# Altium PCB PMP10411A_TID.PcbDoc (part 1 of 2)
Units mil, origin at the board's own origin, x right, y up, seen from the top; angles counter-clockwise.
Board outline 3000 x 2000 mil, 4 copper layers (Top Layer, Signal Layer 1, Signal Layer 2, Bottom Layer), stack 63.634 mil thick; 167 components, 63 nets, 404 pads, 19 vias.
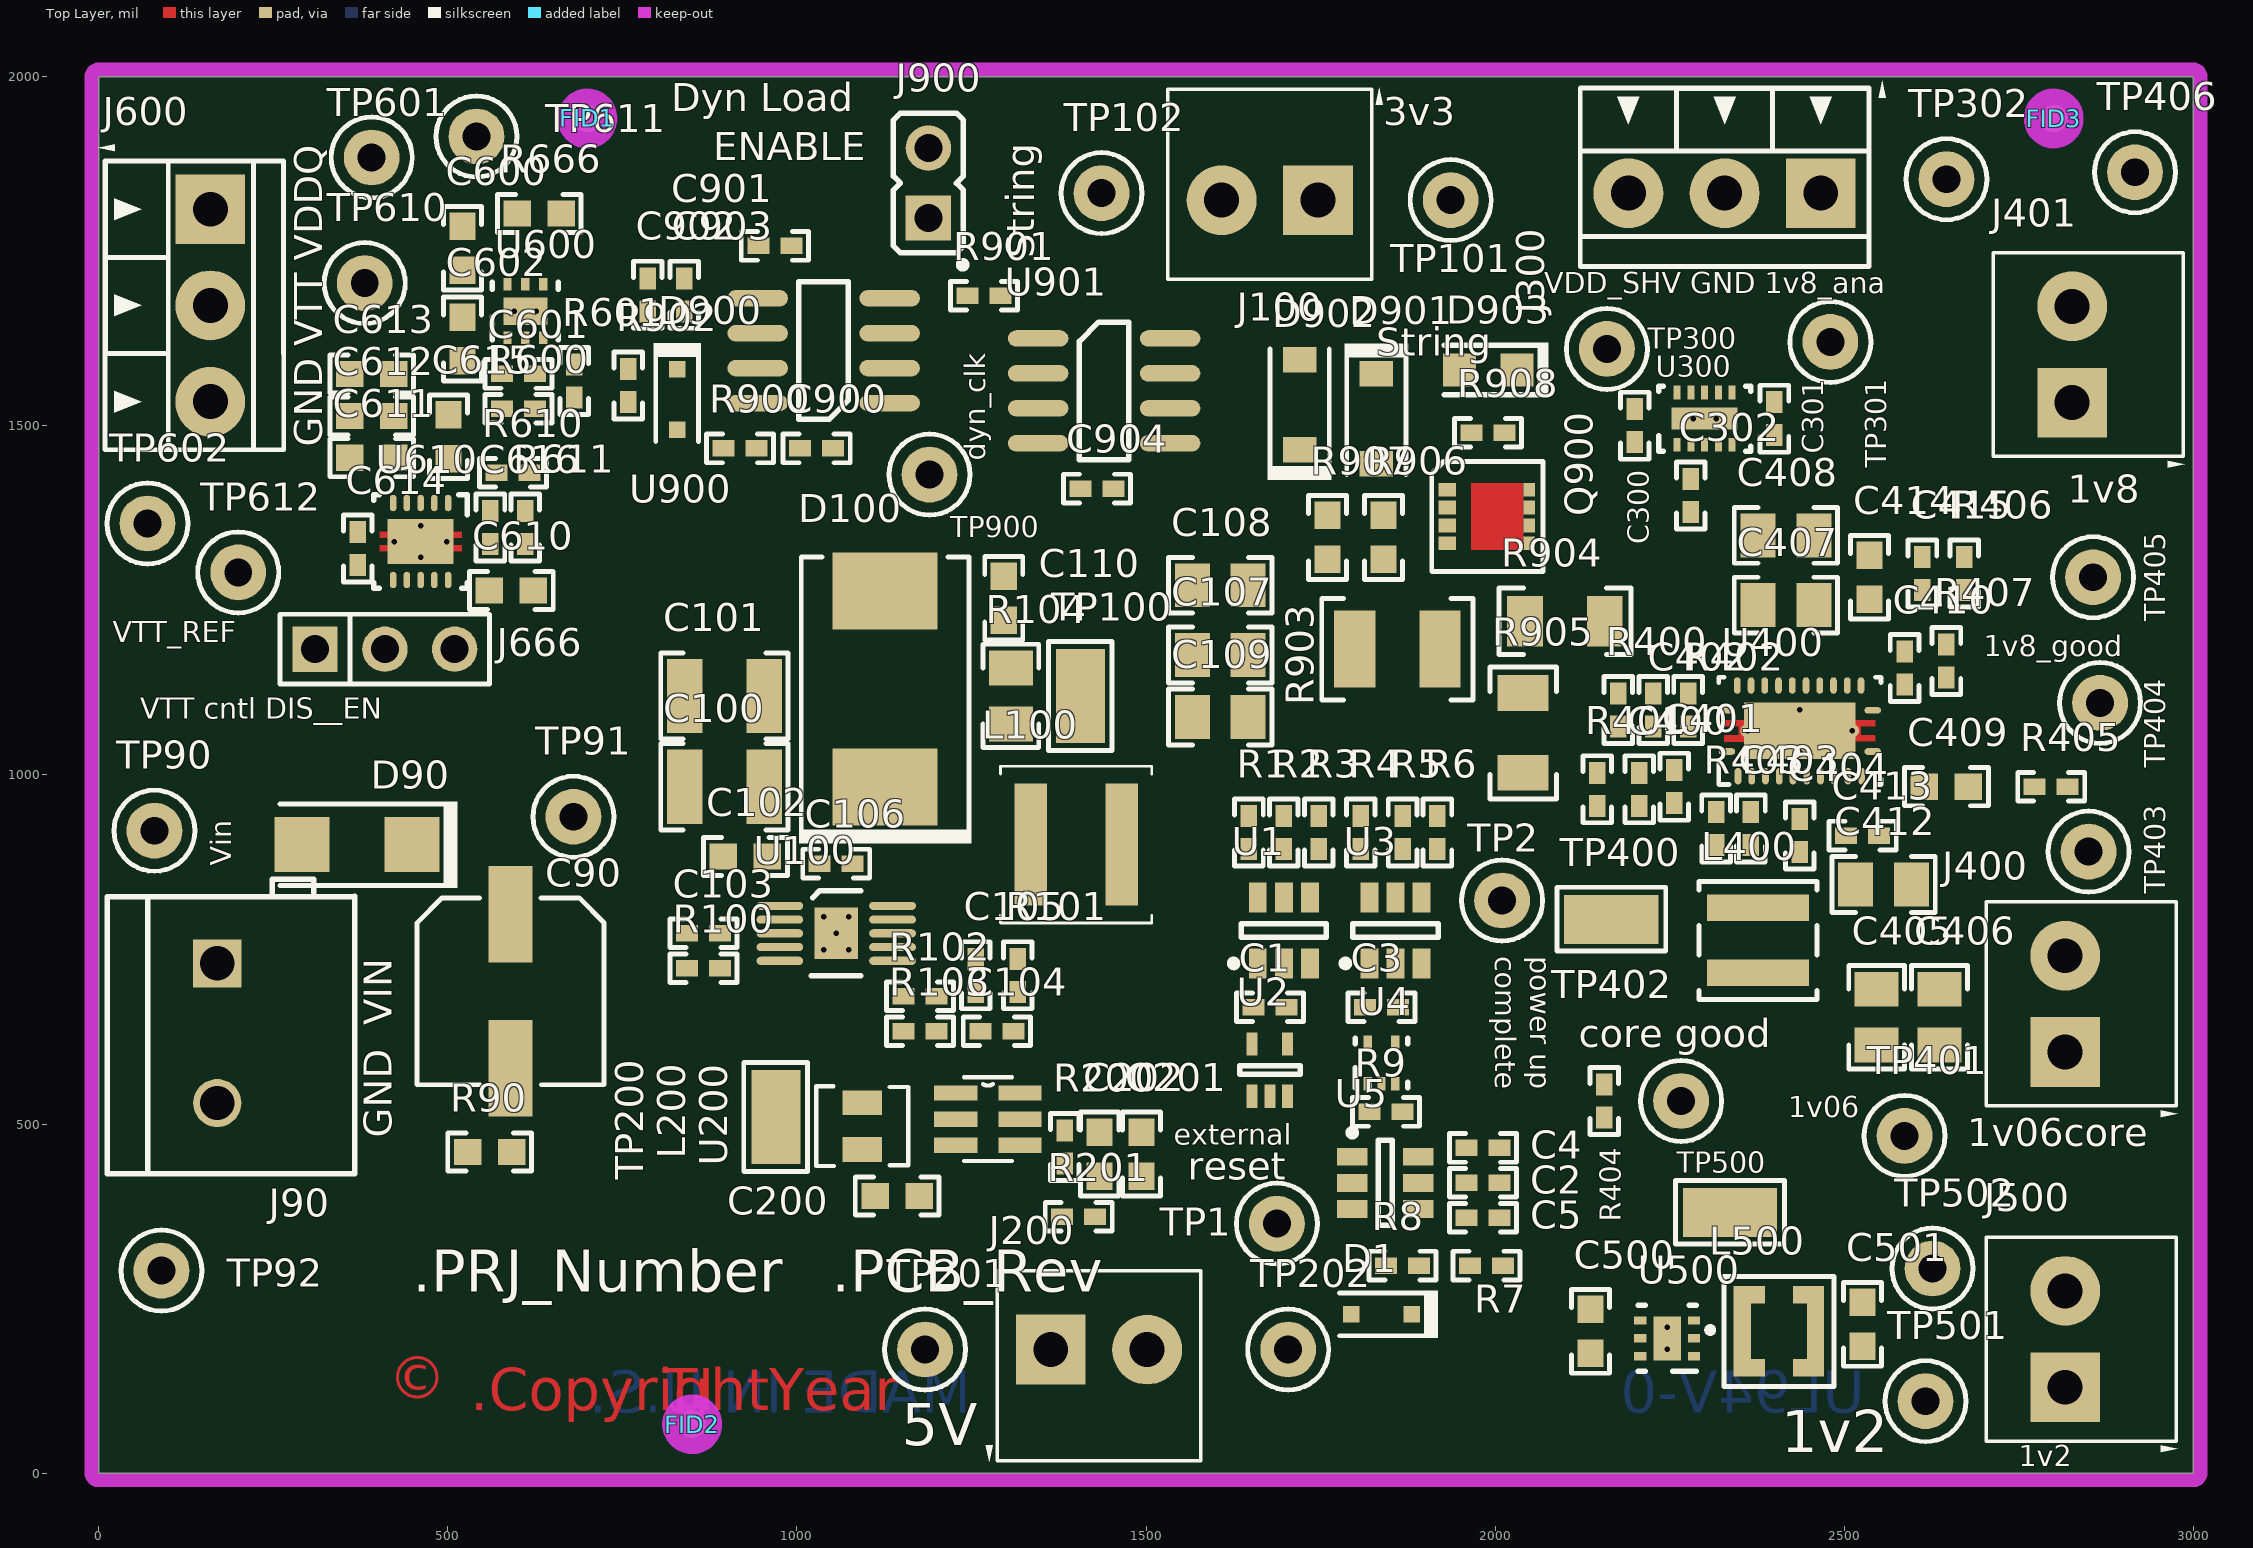
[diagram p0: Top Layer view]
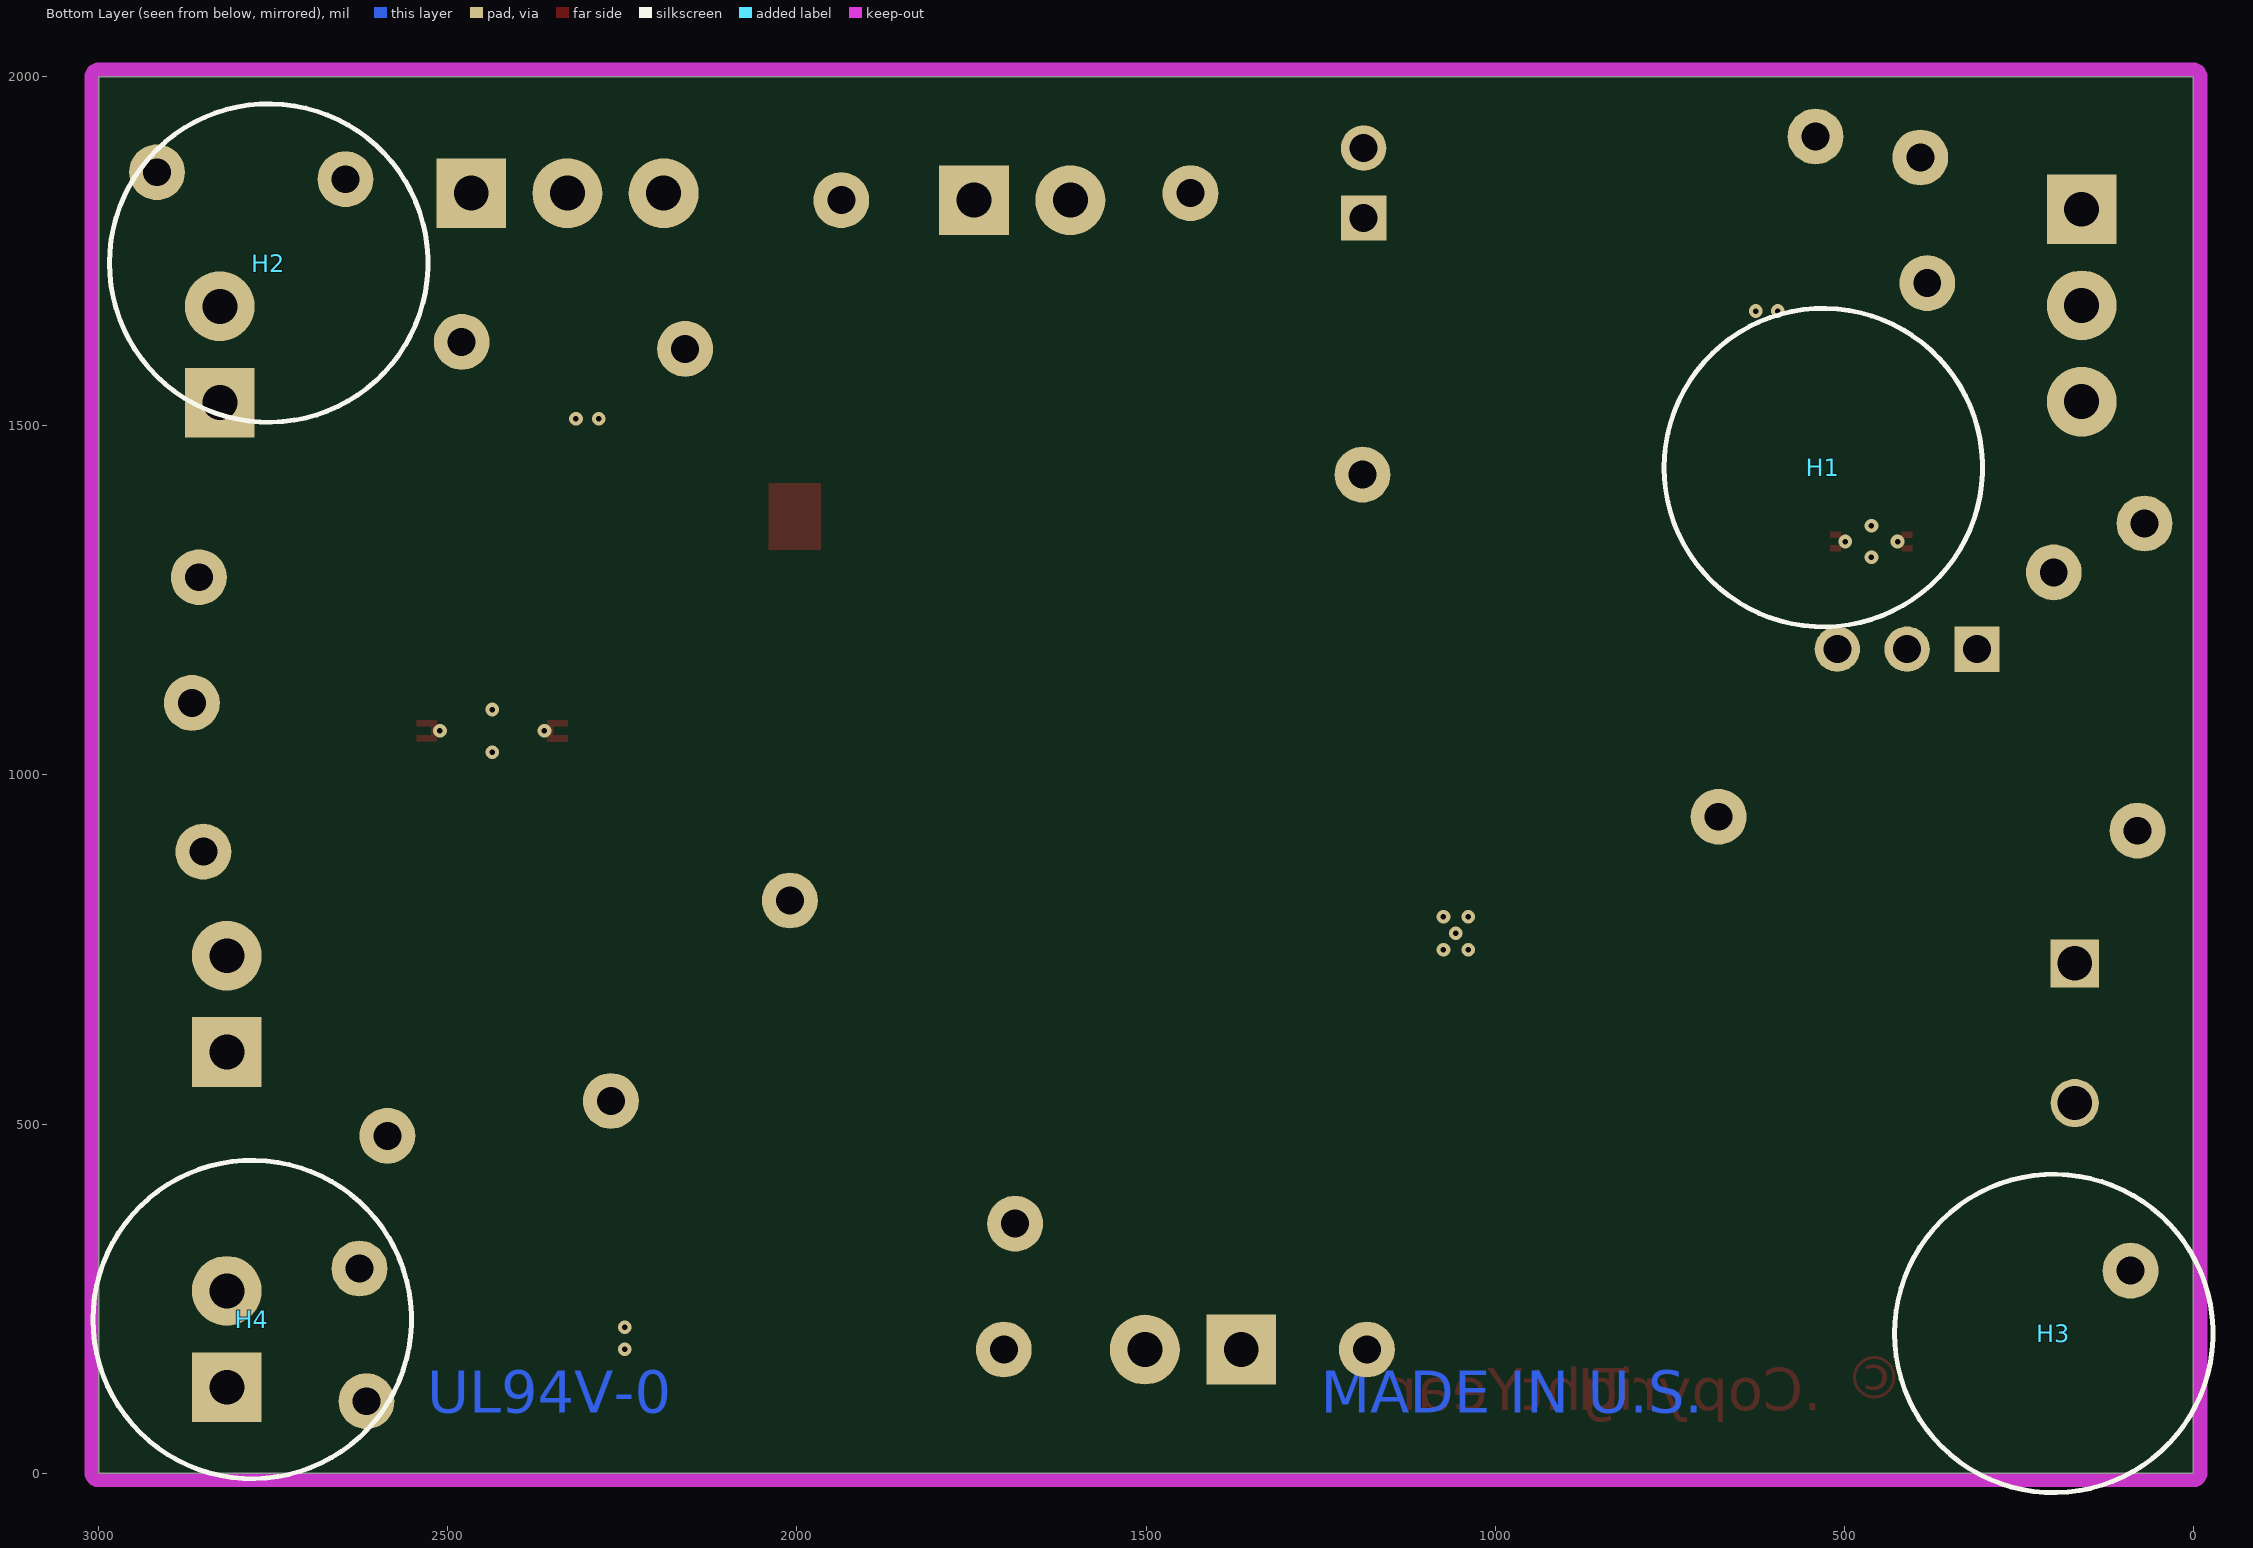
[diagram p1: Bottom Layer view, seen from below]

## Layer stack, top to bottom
Top Solder: solder mask 0.4, Solder Resist, Dk 3.5
Top Layer: signal copper 1.4
Dielectric1: core 20, FR-4, Dk 4.8
Signal Layer 1: signal copper 1.417
Dielectric 3: prepreg 18, Dk 4.2
Signal Layer 2: signal copper 1.417
Dielectric 2: core 20, Dk 4.2
Bottom Layer: signal copper 1.4
Bottom Solder: solder mask 0.4, Solder Resist, Dk 3.5

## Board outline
0,0 3000,0 3000,2000 0,2000

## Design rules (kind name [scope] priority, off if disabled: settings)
AcuteAngle [All] p1: minimum=4.50000000000000E+0001 checktracksonly=FALSE
AssemblyTestPointUsage [All] p1: valid=2
Clearance Clearance_Keepouts [((IsTrack Or IsArc) And Not InPoly) And IsFree and IsKeepOut vs ((IsTrack Or IsArc) And Not InPoly) And IsFree and IsKeepOut] p1: gap=0
Clearance Clearance_BoardEdge_MountingHoles [OnCopper and InComponentClass('Mounting Holes') vs IsKeepOut] p2: gap=40
Clearance Clearance_BoardEdge_Poly [OnCopper and InPoly vs IsKeepOut] p3: gap=25
Clearance Clearance_BoardEdge [OnCopper and Not InComponentClass('Logo') and not InComponentClass('FiducialMark') and not InRegion(1000,500,4000,800) and Not IsKeepout vs IsKeepOut] p4: gap=75
Clearance Clearance_Poly [InPolygon] p5: gap=25
Clearance [All] p6: gap=7.87
ComponentClearance ComponentClearance_MountingHoles_FiducialMarks [InComponentClass('Mounting Holes') vs InComponentClass('FiducialMark')] p1: gap=50 collisioncheckmode=3 verticalgap=10 showdistances=FALSE
ComponentClearance ComponentClearance_Shunt [InComponentClass('Header') vs InComponentClass('Shunt')] p2: gap=0 collisioncheckmode=3 verticalgap=0 showdistances=FALSE
ComponentClearance ComponentClearance_Logo [InComponentClass('Logo')] p3: gap=50 collisioncheckmode=3 verticalgap=10 showdistances=FALSE
ComponentClearance ComponentClearance_ScrewToNut [(HasFootprint('NY PMS 440 0025 PH')) vs (HasFootprint('Keystone_1902C'))] p4: gap=5 collisioncheckmode=3 verticalgap=10 showdistances=FALSE
ComponentClearance ComponentClearance_MountingHoles [InComponentClass('Mounting Holes')] p5: gap=250 collisioncheckmode=3 verticalgap=100000 showdistances=FALSE
ComponentClearance ComponentClearance_SmallPassives [HasFootprint('0201*') or HasFootprint('0402*') or HasFootprint('0508') or HasFootprint('0603*') or HasFootprint('0612') or HasFootprint('0805*') or HasFootprint('0815*') or HasFootprint('0830*') or HasFootprint('1206*') or HasFootprint('1210*') or HasFootprint('1808*') or HasFootprint('1812*') or HasFootprint('1825*') or HasFootprint('2010*') or HasFootprint('2220*') or HasFootprint('2225*') or HasFootprint('2512*') or HasFootprint('2728*') or HasFootprint('3518*') vs HasFootprint('0201*') or HasFootprint('0402*') or HasFootprint('0508') or HasFootprint('0603*') or HasFootprint('0612') or HasFootprint('0805*') or HasFootprint('0815*') or HasFootprint('0830*') or HasFootprint('1206*') or HasFootprint('1210*') or HasFootprint('1808*') or HasFootprint('1812*') or HasFootprint('1825*') or HasFootprint('2010*') or HasFootprint('2220*') or HasFootprint('2225*') or HasFootprint('2512*') or HasFootprint('2728*') or HasFootprint('3518*')] p6: gap=20 collisioncheckmode=3 verticalgap=10 showdistances=FALSE
ComponentClearance ComponentClearance_THtoSMT [IsThruComponent vs IsSMTComponent] p7: gap=100 collisioncheckmode=3 verticalgap=30 showdistances=FALSE
ComponentClearance ComponentClearance_THtoTH [IsThruComponent vs IsThruComponent] p8: gap=118.11 collisioncheckmode=3 verticalgap=30 showdistances=FALSE
ComponentClearance [All] p9: gap=40 collisioncheckmode=3 verticalgap=10 showdistances=FALSE
DiffPairsRouting [All] p1: maxlimit=100 minlimit=10 mostfreqgap=10 toplayer_minwidth=15 toplayer_maxwidth=15 toplayer_prefwidth=15 midlayer1_minwidth=15 midlayer1_maxwidth=15 midlayer1_prefwidth=15 midlayer2_minwidth=15 midlayer2_maxwidth=15 midlayer2_prefwidth=15 bottomlayer_minwidth=15 bottomlayer_maxwidth=15 bottomlayer_prefwidth=15 maxuncoupledlength=1000
FabricationTestPointUsage TestPointUsage [All] p1: valid=2 allowmultiple=FALSE
FabricationTestpoint Testpoint [All] p1: side=3 testpointundercomponent=TRUE minsize=40 maxsize=100 preferedsize=60 minholesize=0 maxholesize=40 preferedholesize=32 testpointgrid=1 allowsidetop=TRUE allowsidebottom=TRUE usegrid=TRUE gridtolerance=0.01
FanoutControl Fanout_LCC [IsLCC] p1: bgadir=Out bgaviamode=Centered fanoutstyle=Auto fanoutdirection=Alternating viagrid=1 // Fanout_LCC (Default Rule)
FanoutControl Fanout_BGA [IsBGA] p2: bgadir=Out bgaviamode=Centered fanoutstyle=Auto fanoutdirection=Alternating viagrid=1 // Fanout_BGA (Default Rule)
FanoutControl Fanout_Default [All] p4: bgadir=Out bgaviamode=Centered fanoutstyle=Auto fanoutdirection=Alternating viagrid=1 // Fanout_Default (Default Rule)
FanoutControl Fanout_Small [(CompPinCount < 5)] p5: bgadir=Out bgaviamode=Centered fanoutstyle=Auto fanoutdirection=OutThenIn viagrid=1 // Fanout_Small (Default Rule)
HoleSize [All] p1: absolutevalues=TRUE maxlimit=251 minlimit=8 maxpercent=80.000 minpercent=20.000
MinimumAnnularRing MinimumAnnularRing_ThermalPadVias [IsVia and InAnyComponent] p1: minimumring=5.91
MinimumAnnularRing [All] p2: minimumring=9
MinimumSolderMaskSliver MinimumSolderMaskSliver_Logo [InComponentClass('Logo') vs InComponentClass('Logo')] p1: minsoldermaskwidth=0.7
MinimumSolderMaskSliver [All] p2: minsoldermaskwidth=3.94
PlaneConnect [All] p1: planeconnectstyle=Relief reliefexpansion=10 reliefentries=4 reliefconductorwidth=10 reliefairgap=10
PolygonConnect [All] p1: connectstyle=Relief reliefconductorwidth=10 reliefentries=4 polygonreliefangle="90 Angle" airgapwidth=10
RoutingVias ThermalPadVias [IsVia and InAnyComponent] p1: holewidth=7.87 width=19.68 viastyle="Through Hole" minholewidth=7.87 minwidth=19.68 maxholewidth=12.99 maxwidth=23.62
RoutingVias [All] p2: holewidth=16 width=34 viastyle="Through Hole" minholewidth=7.87 minwidth=26 maxholewidth=40 maxwidth=65
SilkToBoardRegionClearance [Not ((IsComment or IsDesignator) And (Hide <> 'False')) and not InRegion(1000,500,4000,800)] p1:
SilkToSilkClearance SilkToSilkClearance_Pb-FreeLogo [(HasFootprint('Pb-Free_Overlay_Medium') OR HasFootprint('Pb-Free_Overlay_Small')) vs (HasFootprint('Pb-Free_Overlay_Medium') OR HasFootprint('Pb-Free_Overlay_Small'))] p1: silktosilkclearance=0
SilkToSilkClearance [All] p2: silktosilkclearance=5
SilkToSolderMaskClearance "Silk to Solder Mask Opening" [All] p1: minsilkscreentomaskgap=1 clearancetoexposedcopper=FALSE
SolderMaskExpansion [All] p1: expansion=1.97
UnpouredPolygon [All] p1: allowunpoured=FALSE
Width [All] p1: maxlimit=100 minlimit=6 preferedwidth=10 checkconnectedcopper=TRUE
14 further rules are at their usual default settings.

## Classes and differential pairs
net class U610_Nets: 3V3MEM GND NetC614_2 NetC616_1 NetJ666_2 NetU610_9 VDDQ VTT
net class U600_Nets: 3V3MEM EN_2 GND NetC601_2 NetU600_5 VDDQ
net class J666_Nets: 3V3MEM GND NetJ666_2
net class TP612_Nets: NetC614_2
net class TP611_Nets: GND
net class TP610_Nets: VTT
net class TP602_Nets: GND
net class TP601_Nets: VDDQ
net class R666_Nets: 3V3 3V3MEM
net class R611_Nets: GND NetC616_1
net class R610_Nets: NetC616_1 VDDQ
net class R601_Nets: GND NetC601_2
net class R600_Nets: NetC601_2 VDDQ
net class J600_Nets: GND VDDQ VTT
net class C616_Nets: GND NetC616_1
net class C615_Nets: GND VDDQ
net class C614_Nets: GND NetC614_2
net class C613_Nets: GND VTT
net class C612_Nets: GND VTT
net class C611_Nets: GND VTT
net class C610_Nets: 3V3MEM GND
net class C602_Nets: GND VDDQ
net class C601_Nets: NetC601_2 VDDQ
net class C600_Nets: 3V3MEM GND
net class U500_Nets: 1V2 3V3 EN_4 GND NetL500_1
net class U400_Nets: 1V06_GOOD 1V8 1V8_VSENSE 3V3 EN_2 EN_5 GND NetC401_2 NetC402_2 NetC403_2 NetC404_1 NetC404_2 NetC410_2 NetR403_2 NetR405_1 NetU400_14 NetU400_23
net class U300_Nets: 1V8 1V8_ANALOG 3V3 EN_3 EN_6 GND NetU300_7 NetU300_9 VDD_SHV
net class U200_Nets: 3V3 5V GND NetL200_2 NetR200_1
net class U100_Nets: GND NetC103_2 NetC105_2 NetC106_1 NetC106_2 NetR100_2 NetR102_1 NetU100_3 NetU100_6 VIN
net class U5_Nets: 3V3 GND NetC2_2 NetC5_2 NetR9_1 NetTP1_1
net class U4_Nets: 3V3 EN_4 GND NetR9_1 NetU3_3
net class U3_Nets: 3V3 EN_5 EN_6 EN_EXTRA GND NetU3_3
net class U2_Nets: 3V3 EN_5 GND NetR9_1 NetU1_3
net class U1_Nets: 3V3 EN_2 EN_3 EN_4 GND NetU1_3
net class TP502_Nets: GND
net class TP501_Nets: 1V2
net class TP500_Nets: NetL500_1
net class TP406_Nets: GND
net class TP405_Nets: 1V8
net class TP404_Nets: NetR405_1
net class TP403_Nets: GND
net class TP402_Nets: 1V06_GOOD
net class TP401_Nets: 1V06
net class TP400_Nets: NetC404_2
net class TP302_Nets: GND
net class TP301_Nets: 1V8_ANALOG
net class TP300_Nets: VDD_SHV
net class TP202_Nets: GND
net class TP201_Nets: 5V
net class TP200_Nets: NetL200_2
net class TP102_Nets: GND
net class TP101_Nets: 3V3
net class TP100_Nets: NetC106_1
net class TP92_Nets: GND
net class TP91_Nets: VIN
net class TP90_Nets: VIN_P
net class TP2_Nets: EN_EXTRA
net class TP1_Nets: NetTP1_1
net class R407_Nets: 1V8_VSENSE GND
net class R406_Nets: 1V8 1V8_VSENSE
net class R405_Nets: 3V3 NetR405_1
net class R404_Nets: 1V06_GOOD 3V3
net class R403_Nets: GND NetR403_2
net class R402_Nets: GND NetC402_2
net class R401_Nets: NetC400_2 NetC401_2
net class R400_Nets: 1V06 NetC402_2
net class R201_Nets: GND NetR200_1
net class R200_Nets: 5V NetR200_1
net class R104_Nets: NetC106_1 NetC110_1
net class R103_Nets: GND NetR102_1
net class R102_Nets: 3V3 NetR102_1
net class R101_Nets: NetC104_2 NetC105_2
net class R100_Nets: GND NetR100_2
net class R90_Nets: GND NetC90_2
net class R9_Nets: 3V3 NetR9_1
net class R8_Nets: GND NetC2_2
net class R7_Nets: NetC2_2 VIN_P
net class R6_Nets: 3V3 EN_EXTRA
net class R5_Nets: 3V3 EN_6
net class R4_Nets: 3V3 EN_5
net class R3_Nets: 3V3 EN_4
net class R2_Nets: 3V3 EN_3
net class R1_Nets: 3V3 EN_2
net class L500_Nets: 1V2 NetL500_1
net class L400_Nets: 1V06 NetC404_2
net class L200_Nets: 3V3 NetL200_2
net class L100_Nets: 3V3 NetC106_1
net class J500_Nets: 1V2 GND
net class J401_Nets: 1V8 GND
net class J400_Nets: 1V06 GND
net class J300_Nets: 1V8_ANALOG GND VDD_SHV
net class J200_Nets: 5V GND
net class J100_Nets: 3V3 GND
net class J90_Nets: GND VIN_P
net class D100_Nets: GND NetC106_1
net class D90_Nets: VIN VIN_P
net class D1_Nets: GND NetC2_2
net class C501_Nets: 1V2 GND
net class C500_Nets: 3V3 GND
net class C415_Nets: 1V8 1V8_VSENSE
net class C414_Nets: 1V8 GND
net class C413_Nets: 3V3 GND
net class C412_Nets: 3V3 GND
net class C410_Nets: GND NetC410_2
net class C409_Nets: 3V3 GND
net class C408_Nets: 3V3 GND
net class C407_Nets: 3V3 GND
net class C406_Nets: 1V06 GND
net class C405_Nets: 1V06 GND
net class C404_Nets: NetC404_1 NetC404_2
net class C403_Nets: GND NetC403_2
net class C402_Nets: 1V06 NetC402_2
net class C401_Nets: GND NetC401_2
net class C400_Nets: GND NetC400_2
net class C302_Nets: 3V3 GND
net class C301_Nets: 1V8 GND
net class C300_Nets: 3V3 GND
net class C202_Nets: 5V GND
net class C201_Nets: 5V GND
net class C200_Nets: 3V3 GND
net class C110_Nets: GND NetC110_1
net class C109_Nets: 3V3 GND
net class C108_Nets: 3V3 GND
net class C107_Nets: 3V3 GND
net class C106_Nets: NetC106_1 NetC106_2
net class C105_Nets: GND NetC105_2
net class C104_Nets: GND NetC104_2
net class C103_Nets: GND NetC103_2
net class C102_Nets: GND VIN
net class C101_Nets: GND VIN
net class C100_Nets: GND VIN
net class C90_Nets: NetC90_2 VIN
net class C5_Nets: GND NetC5_2
net class C4_Nets: 3V3 GND
net class C3_Nets: 3V3 GND
net class C2_Nets: GND NetC2_2
net class C1_Nets: 3V3 GND
component class PMP10411A_Main3v3&Boost&sequencing: C1 C2 C3 C4 C5 C90 C100 C101 C102 C103 C104 C105 C106 C107 C108 C109 C110 C200 C201 C202 D1 D90 D100 J90 J100 J200 L100 L200 R1 R2 R3 R4 R5 R6 R7 R8 R9 R90 R100 R101 R102 R103 R104 R200 R201 TP1 TP2 TP90 TP91 TP92 TP100 TP101 TP102 TP200 TP201 TP202 U1 U2 U3 U4 U5 U100 U200
component class FiducialMark: FID1 FID2 FID3
component class PMP10411A_LowV_outputs: C300 C301 C302 C400 C401 C402 C403 C404 C405 C406 C407 C408 C409 C410 C412 C413 C414 C415 C500 C501 C600 C601 C602 C610 C611 C612 C613 C614 C615 C616 FID1 FID2 FID3 H1 H2 H3 H4 J300 J400 J401 J500 J600 J666 L400 L500 R400 R401 R402 R403 R404 R405 R406 R407 R600 R601 R610 R611 R666 TP300 TP301 TP302 TP400 TP401 TP402 TP403 TP404 TP405 TP406 TP500 TP501 TP502 TP601 TP602 TP610 TP611 TP612 U300 U400 U500 U600 U610
component class Header: J666 J900
component class PMP10411A_CoverSheet: C900 C901 C902 C903 C904 D900 D901 D902 D903 J900 Q900 R900 R901 R902 R903 R904 R905 R906 R907 R908 TP900 U900 U901
net class C900_Nets: 3V3 GND
net class C901_Nets: GND NetC901_1
net class C902_Nets: GND NetC902_1
net class C903_Nets: GND NetC902_1
net class C904_Nets: 5V GND
net class D900_Nets: NetC902_1 NetD900_2
net class D901_Nets: NetD901_1 NetD901_2
net class D902_Nets: NetD901_1 NetD902_1
net class D903_Nets: NetD901_1 NetD903_2
net class J900_Nets: 3V3 NetJ900_1
net class Q900_Nets: GND NetQ900_4 NetQ900_5
net class R900_Nets: 3V3 NetD900_2
net class R901_Nets: GND NetJ900_1
net class R902_Nets: NetC902_1 NetD900_2
net class R903_Nets: 3V3 NetQ900_5
net class R904_Nets: 1V06 NetQ900_5
net class R905_Nets: 1V2 NetQ900_5
net class R906_Nets: NetD901_2 NetQ900_4
net class R907_Nets: NetD902_1 NetQ900_4
net class R908_Nets: GND NetD903_2
net class TP900_Nets: NetTP900_1
net class U900_Nets: 3V3 GND NetC901_1 NetC902_1 NetD900_2 NetJ900_1 NetTP900_1
net class U901_Nets: 5V GND NetD901_1 NetTP900_1 NetU901_1 NetU901_5 NetU901_8

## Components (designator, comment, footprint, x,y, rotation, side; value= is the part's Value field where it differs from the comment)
C1 "GRM155R61E104KA87D" 0402 1677.4,667.24 r180 top
C2 "GRM1535C1H101JDD5D" 0402 1982.63,415.74 r180 top
C3 "GRM155R61E104KA87D" 0402 1837.4,667.24 r180 top
C4 "GRM155R61E104KA87D" 0402 1982.63,465.74 r180 top
C5 "GRM155R61E104KA87D" 0402 1982.63,365.74 r180 top
C90 "UUD1H470MCL1GS" SM_RADIAL_6.3BMM 590,690 r270 top
C100 "GRM32ER71H106KA12L" 1210 896.35,983 r0 top
C101 "GRM32ER71H106KA12L" 1210 896.35,1113 r0 top
C102 "06035C104KAT2A" 0603 926.35,883 r0 top
C103 "C1005X7R1E103K" 0402 866.35,773 r0 top
C104 "C1005X7R1H332K" 0402 1286.35,633 r0 top
C105 "GRM1535C1H101JDD5D" 0402 1256.35,713 r90 top
C106 "GRM155R61E104KA87D" 0402 1056.35,873 r180 top
C107 "GRM21BR61A226ME44" 0805_HV 1606.35,1171.54 r0 top
C108 "GRM21BR61A226ME44" 0805_HV 1606.35,1271.54 r0 top
C109 "GRM21BR61A226ME44" 0805_HV 1606.35,1083 r0 top
C110 "DNP" 0603 1296.35,1253 r90 top
C200 "CGB3B1X5R1A475K055AC" 0603 1143.65,397 r180 top
C201 "CGB3B1X5R1A475K055AC" 0603 1493.65,457 r270 top
C202 "CGB3B1X5R1A475K055AC" 0603 1433.65,457 r270 top
C300 "GRM155R60J225ME15D" 0402 2200,1500 r90 top
C301 "GRM155R60J225ME15D" 0402 2400,1510 r90 top
C302 "GRM155R60J225ME15D" 0402 2280,1400 r270 top
C400 "GRM155R71H332KA01D" 0402 2206.35,979.38 r270 top
C401 "GRM1555C1E470JA01D" 0402 2256.35,983 r270 top
C402 "GRM155R71H331KA01D" 0402 2226.35,1093 r90 top
C403 "GRM155R71H103KA88D" 0402 2366.35,923 r90 top
C404 "GRM155R61E104KA87D" 0402 2436.35,913 r270 top
C405 "GRM21BR61A226ME44" 0805_HV 2546.35,653 r90 top
C406 "GRM21BR61A226ME44" 0805_HV 2636.35,653 r90 top
C407 "GRM21BR61A226ME44" 0805_HV 2416.35,1243 r180 top
C408 "GRM21BR61A226ME44" 0805_HV 2416.35,1343 r180 top
C409 "CGB3B1X5R1A475K055AC" 0603 2646.35,983 r0 top
C410 "GRM155R71H103KA88D" 0402 2586.35,1153 r90 top
C412 "GRM21BR61A226ME44" 0805_HV 2556.35,843 r0 top
C413 "GRM155R61E104KA87D" 0402 2526.35,913 r180 top
C414 "GRM188R60J475ME19D" 0603 2536.35,1283 r90 top
C415 "GRM155R61E104KA87D" 0402 2611.85,1288.49 r90 top
C500 "GRM188R60J475ME19D" 0603 2136.35,203 r270 top
C501 "GRM188R60J106ME84" 0603 2526.35,213 r90 top
C600 "GRM188R60J106ME84" 0603 521.15,1754.19 r270 top
C601 "GRM1555C1H220JA01D" 0402 601.15,1574.19 r0 top
C602 "GRM188R60J106ME84" 0603 521.15,1624.19 r90 top
C610 "GRM188R60J106ME84" 0603 591.15,1264.19 r0 top
C611 "GRM188R60J106ME84" 0603 391.15,1454.19 r180 top
C612 "GRM188R60J106ME84" 0603 391.15,1514.19 r180 top
C613 "GRM188R60J106ME84" 0603 391.15,1574.19 r180 top
C614 "GRM155R61E104KA87D" 0402 371.15,1324.19 r270 top
C615 "GRM188R60J106ME84" 0603 501.15,1484.19 r90 top
C616 "GRM155R61C102KA01D" 0402 561.15,1354.19 r270 top
C900 "C1005X7R1H104M" 0402 1028.4,1467.52 r0 top
C901 "C1005X7R1H104M" 0402 968.4,1757.52 r0 top
C902 "C1005X7R1H104M" 0402 786.58,1687.52 r90 top
C903 "C1005X7R1H104M" 0402 838.58,1687.52 r90 top
C904 "GRM155R61A105KE15D" 0402 1430,1410 r180 top
D1 "BAT54HT1G" sod-323 1837.4,227.24 r180 top
D90 "MBRA340T3G" SMA 370,900 r180 top
D100 "B360-13-F" SMC 1126.35,1123 r90 top
D900 "BAT54WS-7-F" sod-323 828.4,1537.52 r270 top
D901 "MBR0530T1G" SOD-123 1830,1510 r270 top
D902 "MBR0530T1G" SOD-123 1720,1530 r90 top
D903 "LTST-C170KRKT" LED_LTST-C170 1990,1580 r0 top
FID1 "Fiducial" Fiducial10-20 700,1940 r0 top
FID2 "Fiducial" Fiducial10-20 850,70 r0 top
FID3 "Fiducial" Fiducial10-20 2800,1940 r0 top
H1 "SJ-5303 (CLEAR)" Bumpon_SJ5003Transparent 530,1440 r180 bottom
H2 "SJ-5303 (CLEAR)" Bumpon_SJ5003Transparent 2756.35,1733 r180 bottom
H3 "SJ-5303 (CLEAR)" Bumpon_SJ5003Transparent 200,200 r180 bottom locked
H4 "SJ-5303 (CLEAR)" Bumpon_SJ5003Transparent 2780,220 r180 bottom
J90 "ED120/2DS" CONN_ED120-2DS 170,630 r180 top
J100 "ED555/2DS" TERM_BLK_ED555-2DS 1746.35,1823 r180 top
J200 "ED555/2DS" TERM_BLK_ED555-2DS 1363.65,177 r0 top
J300 "ED555/3DS" TERM_BLK_ED555-3DS 2466.35,1833 r180 top
J400 "ED555/2DS" TERM_BLK_ED555-2DS 2816.35,603 r90 top
J401 "ED555/2DS" TERM_BLK_ED555-2DS 2826.35,1533 r90 top
J500 "ED555/2DS" TERM_BLK_ED555-2DS 2816.35,123 r90 top
J600 "ED555/3DS" TERM_BLK_ED555-3DS 160,1810 r270 top
J666 "PBC03SAAN" PBC03SAAN 410,1180 r0 top
J900 "PBC02SAAN" Sullins_PBC02SAAN 1188.4,1847.52 r180 top
L100 "XAL5050-103MEB" XAL5050 1400,900 r0 top
L200 "VLF302510MT-4R7M" VLF302510 1093.65,497 r90 top
L400 "XAL4030-332MEB" XAL4030 2376.35,763 r270 top
L500 "LPS3015-222MLB" LPS3015 2406.35,203 r0 top
Q900 "CSD16340Q3" TRANS_NexFET_Q3 1990,1370 r0 top
R1 "CRCW0402100KFKED" 0402 1647.4,917.24 r90 top
R2 "CRCW0402100KFKED" 0402 1697.4,917.24 r90 top
R3 "CRCW0402100KFKED" 0402 1747.4,917.24 r90 top
R4 "CRCW0402100KFKED" 0402 1807.4,917.24 r90 top
R5 "CRCW0402100KFKED" 0402 1867.4,917.24 r90 top
R6 "CRCW0402100KFKED" 0402 1917.4,917.24 r90 top
R7 "CRCW0402110KFKED" 0402 1987.4,297.24 r0 top
R8 "CRCW040210K0FKED" 0402 1867.4,297.24 r0 top
R9 "CRCW040210K0FKED" 0402 1843.78,517.24 r0 top
R90 "ERJ-3RQFR22V" 0603 560,460 r0 top
R100 "CRCW0402340KFKED" 0402 866.35,723 r0 top
R101 "CRCW040210K0FKED" 0402 1316.35,713 r90 top
R102 "CRCW040231K6FKED" 0402 1176.35,683 r0 top
R103 "CRCW040210K0FKED" 0402 1176.35,633 r180 top
R104 "DNP" 0805_HV 1306.35,1113 r270 top
R200 "CRCW04021M82FKED" 0402 1383.65,467 r90 top
R201 "CRCW0402200KFKED" 0402 1403.65,367 r180 top
R400 "CRCW04022K80FKED" 0402 2176.35,1093 r90 top
R401 "CRCW04027K68FKED" 0402 2146.35,979.38 r90 top
R402 "CRCW040210K0FKED" 0402 2276.35,1093 r270 top
R403 "CRCW040284K5FKED" 0402 2316.35,923 r90 top
R404 "CRCW040210K0FKED" 0402 2156.35,533 r90 top
R405 "CRCW040210K0FKED" 0402 2796.35,983 r180 top
R406 "CRCW040212K4FKED" 0402 2671.85,1288.49 r90 top
R407 "CRCW040210K0FKED" 0402 2646.35,1163 r90 top
R600 "CRCW0402100KFKED" 0402 601.15,1524.19 r180 top
R601 "CRCW0402392KFKED" 0402 681.15,1564.19 r270 top
R610 "CRCW040210K0FKED" 0402 593.65,1432.69 r180 top
R611 "CRCW040210K0FKED" 0402 611.15,1354.19 r90 top
R666 "CRCW06030000Z0EA" 0603 631.15,1804.19 r180 top
R900 "CRCW04028K06FKED" 0402 918.4,1467.52 r0 top
R901 "CRCW040210K0FKED" 0402 1268,1686 r180 top
R902 "CRCW0402200KFKED" 0402 758.4,1557.52 r270 top
R903 "ERJ-P14J3R3U" 1210M 1860,1180 r180 top
R904 "ERJ-8RQFR68V" 1206 2100,1220 r0 top
R905 "CRCW120610R0FKEA" 1206 2040,1060 r270 top
R906 "CRCW06031K00FKEA" 0603 1840,1340 r270 top
R907 "CRCW06031K00FKEA" 0603 1760,1340 r270 top
R908 "CRCW0402330RJNED" 0402 1990,1490 r0 top
TP1 "5002" Keystone5002 1687.4,357.24 r0 top
TP2 "5002" Keystone5002 2010,820 r270 top
TP90 "5002" Keystone5002 80,920 r0 top
TP91 "5000" Keystone5000 680,940 r0 top
TP92 "5001" Keystone5001 90,290 r0 top
TP100 "5015" Testpoint_Keystone_Miniature 1406.35,1113 r270 top
TP101 "5000" Keystone5000 1936.35,1823 r0 top
TP102 "5001" Keystone5001 1436.35,1833 r0 top
TP200 "5015" Testpoint_Keystone_Miniature 970,510 r270 top
TP201 "5000" Keystone5000 1183.65,177 r180 top
TP202 "5001" Keystone5001 1703.65,177 r270 top
TP300 "5000" Keystone5000 2160,1610 r90 top
TP301 "5004" Keystone5004 2480,1620 r0 top
TP302 "5001" Keystone5001 2646.35,1853 r90 top
TP400 "5015" Testpoint_Keystone_Miniature 2166.35,793 r180 top
TP401 "5000" Keystone5000 2586.35,483 r0 top
TP402 "5002" Keystone5002 2266.35,533 r90 top
TP403 "5001" Keystone5001 2850,890 r90 top
TP404 "5002" Keystone5002 2866.35,1103 r90 top
TP405 "5000" Keystone5000 2856.35,1283 r90 top
TP406 "5001" Keystone5001 2916.35,1863 r90 top
TP500 "5015" Testpoint_Keystone_Miniature 2336.35,373 r180 top
TP501 "5000" Keystone5000 2616.35,103 r0 top
TP502 "5001" Keystone5001 2626.35,293 r90 top
TP601 "5000" Keystone5000 391.15,1884.19 r0 top
TP602 "5001" Keystone5001 70,1360 r90 top
TP610 "5000" Keystone5000 381.15,1704.19 r0 top
TP611 "5001" Keystone5001 541.15,1914.19 r0 top
TP612 "5000" Keystone5000 200,1290 r0 top
TP900 "5000" Keystone5000 1190,1430 r90 top
U1 "LM3880MF-1AA" MF06A_N 1697.4,777.24 r90 top
U2 "SN74AHC1G32TDCKRQ1" DCK0005A_N 1677.4,577.24 r90 top
U3 "LM3880MF-1AA" MF06A_N 1857.4,777.24 r90 top
U4 "SN74AHC1G08DRL" DRL0005A 1837.4,587.24 r90 top
U5 "TPS3808G01DBV" DBV0006A_N 1842.63,415.74 r0 top
U100 "TPS54240DGQR" DGQ0010D_N 1056.35,773 r0 top
U200 "TPS61071DDC" DDC0006A_N 1273.65,507 r0 top
U300 "TPS22968QDMGTQ1" DMG0010A 2300,1510 r90 top
U400 "TPS54122RHL" RHL0024A 2436.35,1063 r90 top
U500 "TPS62262TDRVRQ1" DRV0006A 2246.35,193 r180 top
U600 "TPS79901QDRVRQ1" DRV0006A 611.15,1664.19 r90 top
U610 "TPS51200QDRCRQ1" DRC0010A 461.15,1334.19 r270 top
U900 "TLC555CD" D0008A_N 1038.4,1607.52 r180 top
U901 "UCC27324D" D0008A_N 1440,1550 r0 top

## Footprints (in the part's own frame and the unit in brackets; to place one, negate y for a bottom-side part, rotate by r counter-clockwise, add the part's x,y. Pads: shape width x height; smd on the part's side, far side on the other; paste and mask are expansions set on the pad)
0402 [mm] "0402 from SM-752 data"
  rect 0.8x0.6 smd: 1(-0.6,0) 2(0.6,0)
  silkscreen extent -1.22,-0.52 1.22,0.52, body extent -0.55,-0.3 0.55,0.3, height 0.6
0603 [mm] "0603 from SM-752 data"
  rect 1x0.95 smd: 1(-0.8,0) 2(0.8,0)
  silkscreen extent -1.52,-0.69 1.52,0.69, body extent -0.87,-0.47 0.87,0.47, height 0.85
0805_HV [mil] "0805 with 30mil clearance between pads"
  rect 50x63 smd: 1(-40,0) 2(40,0)
  silkscreen extent -74,-40 74,40, body extent -43,-29 43,29, height 43
1206 [mm] "1206 from SM-752 data"
  rect 1.3x1.85 smd: 1(-1.45,0) 2(1.45,0)
  silkscreen extent -2.4,-1.21 2.4,1.21, body extent -1.7,-0.9 1.7,0.9, height 1.35
1210 [mm] "1210 from SM-752 data"
  rect 1.3x2.7 smd: 1(-1.45,0) 2(1.45,0)
  silkscreen extent -2.32,-1.57 2.32,1.57, body extent -1.7,-1.35 1.7,1.35, height 1.35
1210M [mm] "1210 from SM-752 data"
  rect 1.5x2.8 smd: 1(-1.55,0) 2(1.55,0)
  silkscreen extent -2.75,-1.85 2.75,1.85, body extent -1.7,-1.35 1.7,1.35, height 1.35
Bumpon_SJ5003Transparent [mil] "3M Hemispherical Bumpon transparent"
  round 1 on Mech4: 0(0,0)
  silkscreen extent -228,-228 228,228, body extent -217,-218 219,218, height 197
CONN_ED120-2DS [mm] "ONSHORE"
  rect 1.75x1.75 hole 1.25: 1(0,-2.54)
  round 1.75 hole 1.25: 2(0,2.54)
  silkscreen extent -5,-5.6 4,5.12, body extent -5,-5.6 4.15,5.12, height 13.1
D0008A_N [mm] "SOIC, 8-Leads, Body 4.9x3.9mm, Pitch 1.27mm, IPC Medium Density"
  oval 2.2x0.6 smd: 1(-2.4,1.905) 2(-2.4,0.635) 3(-2.4,-0.635) 4(-2.4,-1.905) 5(2.4,-1.905) 6(2.4,-0.635) 7(2.4,0.635) 8(2.4,1.905)
  silkscreen extent -0.9,-2.5 0.9,2.5, body extent -3,-2.45 3,2.45, height 1.63
DBV0006A_N [mm] "SOT23, 6-Leads, Body 2.9x1.6mm, Pitch 0.95mm, Lead Span 2.8mm, IPC Medium Density"
  rect 1.1x0.65 smd: 1(-1.2,0.95) 2(-1.2,0) 3(-1.2,-0.95) 4(1.2,-0.95) 5(1.2,0) 6(1.2,0.95)
  silkscreen extent -1.32,-1.55 0.25,1.95, body extent -1.42,-1.46 1.42,1.46, height 1.11
DCK0005A_N [mm] "SOT353, 5-Leads, Body 2x1.3mm, Pitch 0.65mm, Lead Span 2.1mm, IPC Medium Density"
  rect 0.85x0.4 smd: 1(-0.95,0.65) 2(-0.95,0) 3(-0.95,-0.65) 4(0.95,-0.65) 5(0.95,0.65)
  silkscreen extent -0.15,-1.1 0.15,1.1, body extent -1.14,-1 1.14,1, height 0.94
DDC0006A_N [mil]
  rect 62x22 smd: 1(-46,37.4) 2(-46,0) 3(-46,-37.4) 4(46,-37.4) 5(46,0) 6(46,37.4)
  silkscreen extent -34,-60 34,60, body extent -56,-58 56,58, height 35
DGQ0010D_N [mm] "TSSOP, 10-Leads, Body 3x3mm, Pitch 0.5mm, Thermal Pad 1.88x1.57mm, IPC Medium Density"
  oval 1.7x0.3 smd: 1(-2.05,1) 2(-2.05,0.5) 3(-2.05,0) 4(-2.05,-0.5) 5(-2.05,-1) 6(2.05,-1) 7(2.05,-0.5) 8(2.05,0) 9(2.05,0.5) 10(2.05,1)
  rect 1.57x1.88 smd: 11(0,0)
  silkscreen extent -0.9,-1.55 0.9,1.55, body extent -1.55,-1.55 1.55,1.55, height 1.1
DMG0010A [mm] "SON, 10-Leads, Body 2.1x3.1mm, Pitch 0.5mm, Thermal Pad 2.4x0.8mm"
  rect 0.5x0.25 smd: 1(-0.95,1) 2(-0.95,0.5) 3(-0.95,0) 4(-0.95,-0.5) 5(-0.95,-1) 6(0.95,-1) 7(0.95,-0.5) 8(0.95,0) 9(0.95,0.5) 10(0.95,1)
  rect 0.8x2.4 smd paste-0.42: 11(0,0)
  silkscreen extent -1.17,-1.68 1.17,1.68, body extent -1.05,-1.55 1.05,1.55, height 0.81
DRC0010A [mm] "SON, 10-Leads, Body 3x3mm, Pitch 0.5mm, Thermal Pad 2.4x1.65mm, TI Recommended"
  oval 0.6x0.24 smd: 1(-1.4,1) 2(-1.4,0.5) 3(-1.4,0) 4(-1.4,-0.5) 5(-1.4,-1) 6(1.4,-1) 7(1.4,-0.5) 8(1.4,0) 9(1.4,0.5) 10(1.4,1)
  rect 1.65x2.4 smd paste-0.825: 11(0,0)
  Top Layer region: 0.135,-1.5 0.365,-1.5 0.365,-1.1 0.135,-1.1
  Top Layer region: -0.135,-1.1 -0.365,-1.1 -0.365,-1.5 -0.135,-1.5
  Top Layer region: -0.135,1.5 -0.365,1.5 -0.365,1.1 -0.135,1.1
  Top Layer region: 0.135,1.1 0.365,1.1 0.365,1.5 0.135,1.5
  silkscreen extent -1.7,-1.7 1.7,1.7, body extent -1.55,-1.55 1.55,1.55, height 1.01
DRL0005A [mm] "SOTFL, 5-Flat Leads, Body 1.2x1.6x0.6mm, Pitch 0.5mm, TI recommended"
  rect 0.5x0.3 smd: 1(-0.75,0.5) 2(-0.75,0) 3(-0.75,-0.5) 4(0.75,-0.5) 5(0.75,0.5)
  silkscreen extent -0.9,-0.95 0.9,0.95, body extent -0.85,-0.85 0.85,0.85, height 0.62
DRV0006A [mm] "SON, 6-Leads, Body 2x2mm, Pitch 0.65mm, Thermal Pad 1.6x1mm, TI Recommended"
  rect 0.45x0.3 smd: 1(-0.975,0.65) 2(-0.975,0) 3(-0.975,-0.65) 4(0.975,-0.65) 5(0.975,0) 6(0.975,0.65)
  rect 1x1.6 smd paste-0.5: 7(0,0)
  silkscreen extent -1.05,-1.2 1.05,1.2, body extent -1.05,-1.05 1.05,1.05, height 0.81
Fiducial10-20 [mm]
  round 1 smd mask+0.5: 1(0,0)
  Top Layer keep-out circle w1.178: c0,0 r0.5
Keystone5000 [mil] "For Keystone 500x miniature loop terminals"
  round 80 hole 40: 1(0,0)
  silkscreen extent -58,-58 58,58, body extent -49,-49 49,49, height 182
Keystone5001 [mil] "For Keystone 500x miniature loop terminals"
  round 80 hole 40: 1(0,0)
  silkscreen extent -58,-58 58,58, body extent -49,-49 49,49, height 182
Keystone5002 [mil] "For Keystone 500x miniature loop terminals"
  round 80 hole 40: 1(0,0)
  silkscreen extent -58,-58 58,58, body extent -49,-49 49,49, height 182
Keystone5004 [mil] "For Keystone 500x miniature loop terminals"
  round 80 hole 40: 1(0,0)
  silkscreen extent -58,-58 58,58, body extent -49,-49 49,49, height 182
LED_LTST-C170 [mm] "LITE-ON"
  rect 1.2x1.2 smd: 1(-1.05,0) 2(1.05,0)
  silkscreen extent -1.6,-1 2.2,1, body extent -1.05,-0.67 1.05,0.67, height 1.1
LPS3015 [mm] "Coilcraft recommended land pattern.  Document 436-2, rev 12/3/08"
  rect 0.63x3.3 smd: 1(-1.335,0) 2(1.335,0)
  rect 1.14x0.64 smd: 1(-1.08,-1.33) 1(-1.08,1.33) 2(1.08,-1.33) 2(1.08,1.33)
  silkscreen extent -2.59,-2 2,2, body extent -1.58,-1.58 1.58,1.58, height 1.52
MF06A_N [mm] "SOT23, 6-Leads, Body 2.9x1.6mm, Pitch 0.95mm, Lead Span 2.8mm, IPC Medium Density"
  rect 1.1x0.65 smd: 1(-1.2,0.95) 2(-1.2,0) 3(-1.2,-0.95) 4(1.2,-0.95) 5(1.2,0) 6(1.2,0.95)
  silkscreen extent -1.32,-1.55 0.25,1.95, body extent -0.9,-1.55 0.9,1.55, height 1.22
PBC03SAAN [mm] "Sullins 100mil, 1x3, 230 mil above insulator"
  rect 1.65x1.65 hole 1.016: 1(-2.54,0)
  round 1.65 hole 1.016: 2(0,0) 3(2.54,0)
  silkscreen extent -3.81,-1.27 3.81,1.27, body extent -3.81,-1.27 3.81,1.27, height 8.38
RHL0024A [mm]
  oval 0.24x0.6 smd: 1(-0.75,2.65) 12(-0.75,-2.65) 13(0.75,-2.65) 24(0.75,2.65)
  oval 0.6x0.24 smd: 2(-1.65,2.25) 3(-1.65,1.75) 4(-1.65,1.25) 5(-1.65,0.75) 6(-1.65,0.25) 7(-1.65,-0.25) 8(-1.65,-0.75) 9(-1.65,-1.25) 10(-1.65,-1.75) 11(-1.65,-2.25) 14(1.65,-2.225) 15(1.65,-1.725) 16(1.65,-1.225) 17(1.65,-0.725) 18(1.65,-0.225) 19(1.65,0.275) 20(1.65,0.775) 21(1.65,1.275) 22(1.65,1.775) 23(1.65,2.275)
  rect 2.05x4.05 smd paste-1.1: 25(0,0)
  Top Layer region: -0.395,-2.225 0.395,-2.225 0.395,-2.024 -0.395,-2.024
  Top Layer region: -0.396,2 -0.154,2 -0.154,2.75 -0.396,2.75
  Top Layer region: 0.152,2 0.394,2 0.394,2.75 0.152,2.75
  Top Layer region: -0.395,2.024 0.395,2.024 0.395,2.225 -0.395,2.225
  Top Layer region: -0.152,-2 -0.394,-2 -0.394,-2.75 -0.152,-2.75
  Top Layer region: 0.396,-2 0.154,-2 0.154,-2.75 0.396,-2.75
  silkscreen extent -1.95,-2.95 1.95,2.95, body extent -1.82,-2.82 1.82,2.82, height 1.01
SM_RADIAL_6.3BMM [mm] "Nichicon 6.3x7.7"
  rect 3.5x1.6 smd: 1(-2.8,0) 2(2.8,0)
  silkscreen extent -3.4,-3.4 3.4,3.4, body extent -3.41,-3.41 3.41,3.41, height 8
SMA [mm] "Molded Diode, 2-Leads, Body 4.3x2.6mm, IPC Medium Density, based on OnSemi component dimensions and land pattern"
  rect 2x2 smd: 1(-2,0) 2(2,0)
  silkscreen extent -3.66,-1.57 2.79,1.57, body extent -2.6,-1.3 2.6,1.3, height 2.42
SMC [mil] "Molded Diode, 2-Leads, Body 6.9x5.8mm, IPC Medium Density, based on OnSemi component dimensions and land patterns"
  rect 110x150 smd: 1(-140.49,0) 2(140.49,0)
  silkscreen extent -221,-124 189,123, body extent -156,-116 156,116, height 91
SOD-123 [mm] "On Semi recommended land pattern"
  rect 0.915x1.22 smd: 1(-1.637,0) 2(1.637,0)
  silkscreen extent -2.74,-1.17 2.03,1.17, body extent -1.93,-0.9 1.93,0.9, height 1.35
sod-323 [mm] "NXP recommended land pattern"
  rect 0.6x0.6 smd paste-0.05: 1(-1.1,0) 2(1.1,0)
  silkscreen extent -2.06,-0.86 1.53,0.86, body extent -1.3,-0.67 1.3,0.68, height 1.1
Sullins_PBC02SAAN [mm] "Sullins 100mil, 1x2, 230 mil above insulator"
  rect 1.65x1.65 hole 1.016: 1(0,1.27)
  round 1.65 hole 1.016: 2(0,-1.27)
  silkscreen extent -1.37,-2.54 1.27,3.1, body extent -1.27,-2.54 1.27,2.54, height 8.38
TERM_BLK_ED555-2DS [mil]
  rect 100x100 hole 50: 1(0,0)
  round 100 hole 50: 2(138,0)
  silkscreen extent -93,-161 215,113, body extent -69,-150 207,106, height 323
TERM_BLK_ED555-3DS [mm]
  rect 2.54x2.54 hole 1.27: 1(0,0)
  round 2.54 hole 1.27: 2(3.5,0) 3(7,0)
  silkscreen extent -2.36,-4.09 8.75,2.67, body extent -1.75,-3.83 8.75,2.67, height 8.2
Testpoint_Keystone_Miniature [mil] "Miniature SMT test point"
  rect 135x70 smd: 1(0,0)
  silkscreen extent -78,-46 78,45, body extent -52,-20 52,20, height 61
TRANS_NexFET_Q3 [mm] "TI recommended land pattern (nominal) M0143-01"
  rect 0.63x0.5 smd mask+0.076: 1(-1.49,0.975) 2(-1.49,0.325) 3(-1.49,-0.325) 4(-1.49,-0.975)
  rect 0.41x0.5 smd mask+0.076: 5(1.49,-0.975) 6(1.49,-0.325) 7(1.49,0.325) 8(1.49,0.975)
  Top Layer region: -0.615,-1.225 1.285,-1.225 1.285,1.225 -0.615,1.225
  silkscreen extent -2.05,-2 2,2, body extent -1.76,-1.7 1.66,1.7, height 1.11
VLF302510 [mm] "TDK"
  rect 0.9x1.45 smd: 1(-0.85,0) 2(0.85,0)
  silkscreen extent -1.45,-1.68 1.45,1.68, body extent -1.35,-1.6 1.35,1.6, height 1
XAL4030 [mil] "Coilcraft XAL4030 7/18/12"
  rect 38x146 smd: 1(-46.5,0) 2(46.5,0)
  silkscreen extent -85,-85 85,85, body extent -84,-84 84,84, height 122
XAL5050 [mm] "CoilCraft XAL5050 5.28 x 5.48 x 5.1 mm"
  rect 1.18x4.44 smd: 1(-1.655,0) 2(1.655,0)
  silkscreen extent -2.75,-2.85 2.75,2.85, body extent -2.74,-2.84 2.74,2.84, height 5.1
